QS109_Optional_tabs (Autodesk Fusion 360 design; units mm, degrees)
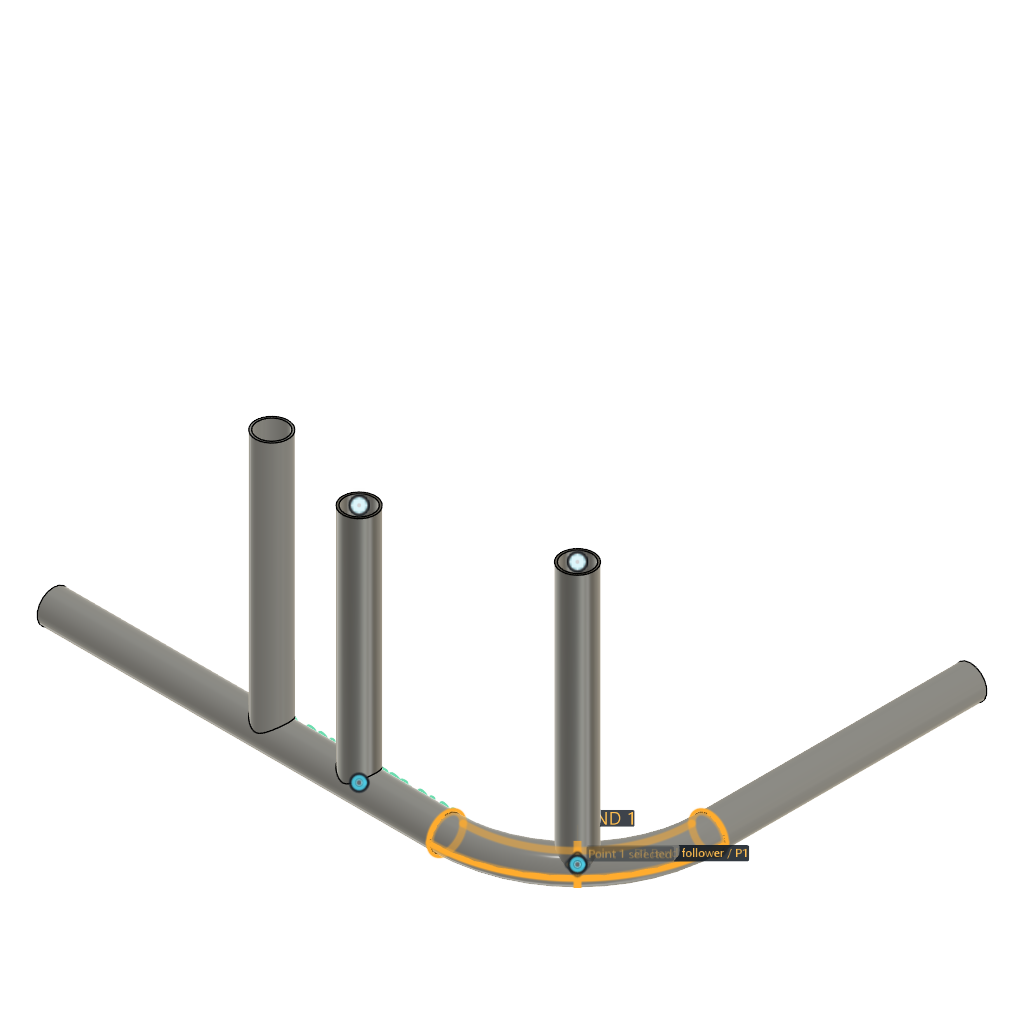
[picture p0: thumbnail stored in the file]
description: Part Number
part number: 2026-10-26-11-38-19-526
parameter "OD_DEMO_ONLY_1_5_x_095_R6" = 38.1
parameter "Wall_DEMO_ONLY_1_5_x_095_R6" = 2.413
base_feature "Base Feature1" bodies "H1 Bent host", "I1 Imported coped brace"
sketch "Tube points" plane through (0, 0, 0) normal (0, 0, 1) x axis (1, 0, 0)
sketch "TubePoints" plane through (0, 0, 0) normal (0, 0, 1) x axis (1, 0, 0)
work_plane "WorkPlane1" ExtraOffset 0
sketch "Sketch3" plane through (564.9631, 44.6369, 0) normal (0, 0, 1) x axis (0, 1, 0)
  circle C1 centre (0, 0) radius 19.05
  circle C2 centre (0, 0) radius 16.637
sketch "TubePoints (1)" plane through (0, 0, 0) normal (0, 0, 1) x axis (1, 0, 0)
work_plane "WorkPlane2" ExtraOffset 0
sketch "Sketch5" plane through (355.6, 0, 0) normal (0, 0, 1) x axis (0, 1, 0)
  circle C1 centre (0, 0) radius 19.05
  circle C2 centre (0, 0) radius 16.637
sketch "TubePoints (2)" plane through (0, 0, 0) normal (0, 0, 1) x axis (1, 0, 0)
work_plane "WorkPlane3" ExtraOffset 0
sketch "Sketch7" plane through (564.9631, 44.6369, 0) normal (0, 0, 1) x axis (0, 1, 0)
  circle C1 centre (0, 0) radius 19.05
  circle C2 centre (0, 0) radius 16.637
  dimension "d21" diameter C1 = 38.1 (= "OD_DEMO_ONLY_1_5_x_095_R6")
  dimension "d22" diameter C2 = 33.274 (= "OD_DEMO_ONLY_1_5_x_095_R6 - 2 * Wall_DEMO_ONLY_1_5_x_095_R6")
sweep "Sweep3" sketch "Sketch7" TwistAngle 0 TaperAngle 0 bodies "B1 Bend follower"
sketch "TubePoints (3)" plane through (0, 0, 0) normal (0, 0, 1) x axis (1, 0, 0)
work_plane "WorkPlane4" ExtraOffset 0
sketch "Sketch9" plane through (355.6, 0, 0) normal (0, 0, 1) x axis (0, 1, 0)
  circle C1 centre (0, 0) radius 19.05
  circle C2 centre (0, 0) radius 16.637
  dimension "d31" diameter C1 = 38.1 (= "OD_DEMO_ONLY_1_5_x_095_R6")
  dimension "d32" diameter C2 = 33.274 (= "OD_DEMO_ONLY_1_5_x_095_R6 - 2 * Wall_DEMO_ONLY_1_5_x_095_R6")
sweep "Sweep4" sketch "Sketch9" TwistAngle 0 TaperAngle 0 bodies "B2 Straight joint"
base_feature "Base Feature2"
surface_stitch "SurfaceStitch1" StitchingTolerence 0.01 bodies "normcope_B2_Straight_joint_A"
split "Split1" bodies "B2 Straight joint"
remove_body "RemoveBody1"
remove_body "RemoveBody2"
base_feature "Base Feature3"
combine "Combine1"
named bodies: "H1 Bent host", "I1 Imported coped brace", "B1 Bend follower", "B2 Straight joint", "normcope_B2_Straight_joint_A"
